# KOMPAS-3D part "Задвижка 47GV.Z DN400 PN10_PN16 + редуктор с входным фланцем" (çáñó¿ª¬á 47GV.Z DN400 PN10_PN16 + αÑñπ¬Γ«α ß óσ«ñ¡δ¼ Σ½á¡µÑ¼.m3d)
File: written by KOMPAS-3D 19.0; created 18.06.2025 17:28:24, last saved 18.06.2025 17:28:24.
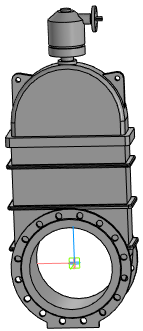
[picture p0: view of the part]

Document properties: Полное имя файла: Задвижка 47GV.Z DN400 PN10_PN16 + редуктор с входным фланцем.a3d

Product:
- Part/product: Задвижка 47GV.Z DN400 PN10_PN16 + редуктор с входным фланцем
    Масса: 780.054

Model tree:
1. Операция без истории:1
